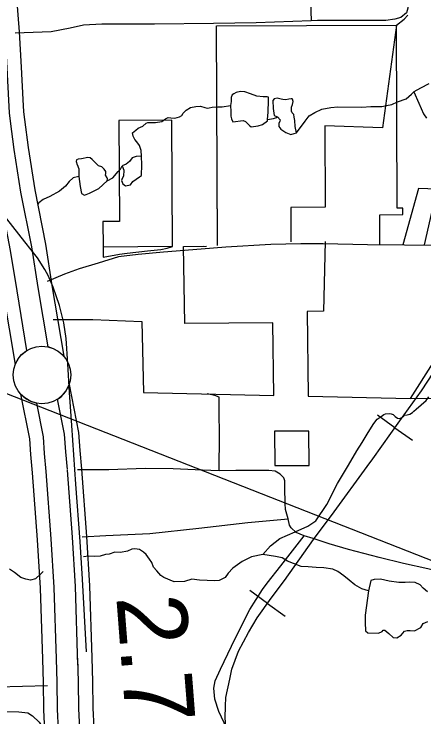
# Model space of a CAD drawing. Extents: x 22866 to 28196, y 1324810 to 1328105.
# Drawn here: x 25705 to 25764.8, y 1326340.7 to 1326443.3 of the extents above; entities that cross this region are included whole.
import ezdxf

# ---------------------------------------------------------------- set-up
doc = ezdxf.new("R2010")
doc.units = 0
for name, color, linetype in [('Level 15', 7, 'Continuous'), ('Level 24', 7, 'Continuous'), ('Level 33', 7, 'Continuous'), ('Level 35', 7, 'Continuous'), ('Level 40', 7, 'Continuous'), ('Level 48', 7, 'Continuous'), ('Level 5', 7, 'Continuous'), ('Level 6', 7, 'Continuous'), ('Page Text', 7, 'Continuous')]:
    doc.layers.add(name, color=color, linetype=linetype)

msp = doc.modelspace()

# ---------------------------------------------------------------- linework, layer by layer
at = {"layer": 'Level 15'}
for points in [[(25705.13, 1326448.21), (25705.72, 1326440.72), (25706.02, 1326435.56), (25706.28, 1326430.85), (25706.38, 1326429.05), (25706.49, 1326427.91), (25707.03, 1326423.82), (25708.01, 1326417.65), (25709.58, 1326409.7), (25710.51, 1326403.7), (25712.25, 1326393.35)], [(25697.94, 1326447.76), (25698.53, 1326440.23), (25698.83, 1326435.16), (25699.09, 1326430.45), (25699.2, 1326428.49), (25699.34, 1326427.08), (25699.9, 1326422.79), (25700.92, 1326416.4), (25702.48, 1326408.44), (25703.41, 1326402.55), (25705.15, 1326392.16), (25705.7, 1326393.12), (25706.12, 1326393.62), (25706.87, 1326394.21)], [(25706.87, 1326394.21), (25705.42, 1326402.88), (25704.49, 1326408.8), (25702.92, 1326416.75), (25701.92, 1326423.08), (25701.37, 1326427.32), (25701.23, 1326428.65), (25701.13, 1326430.57), (25700.86, 1326435.27), (25700.57, 1326440.37), (25699.98, 1326447.89)], [(25712.25, 1326393.35), (25711.41, 1326394.06), (25710.73, 1326394.44), (25709.95, 1326394.72), (25708.5, 1326403.37), (25707.57, 1326409.34), (25706, 1326417.3), (25705.01, 1326423.53), (25704.47, 1326427.68), (25704.34, 1326428.89), (25704.24, 1326430.74), (25703.98, 1326435.45), (25703.68, 1326440.58), (25703.09, 1326448.08)], [(25711.35, 1326387.1), (25711.86, 1326387.44), (25712.52, 1326388.22), (25713.01, 1326389.2), (25714.4, 1326382.23), (25714.57, 1326379.57), (25714.83, 1326376.86)], [(25708.29, 1326386.49), (25707.42, 1326386.73), (25706.57, 1326387.25), (25705.95, 1326387.79), (25707.24, 1326381.29), (25707.39, 1326378.99), (25707.65, 1326376.34)], [(25709.68, 1326376.49), (25709.42, 1326379.16), (25709.27, 1326381.56), (25708.29, 1326386.49)], [(25712.79, 1326376.83), (25712.53, 1326379.41), (25712.37, 1326381.96), (25711.35, 1326387.1)], [(25707.65, 1326376.34), (25708.36, 1326366.55), (25708.81, 1326359.49), (25709.14, 1326349.1)], [(25711.18, 1326349.16), (25710.85, 1326359.58), (25710.39, 1326366.69), (25709.68, 1326376.49)], [(25714.29, 1326348.23), (25713.96, 1326359.73), (25713.51, 1326366.9), (25712.8, 1326376.71)], [(25714.83, 1326376.86), (25715.54, 1326367.04), (25716, 1326359.83), (25716.34, 1326349.31)], [(25709.14, 1326349.1), (25709.24, 1326345.7), (25709.3, 1326341.72), (25709.43, 1326338.66)], [(25711.47, 1326338.79), (25711.34, 1326341.78), (25711.28, 1326345.74), (25711.18, 1326349.16)], [(25714.58, 1326339), (25714.46, 1326341.87), (25714.4, 1326345.81), (25714.3, 1326349.25)], [(25716.34, 1326349.31), (25716.44, 1326345.86), (25716.5, 1326341.93), (25716.62, 1326339.14)]]:
    msp.add_lwpolyline(points, dxfattribs=at)
at = {"layer": 'Level 24'}
msp.add_circle((25709.06, 1326390.62), 4.2, dxfattribs=at)
at = {"layer": 'Level 33'}
for points in [[(25762.61, 1326449.5), (25762.56, 1326446.04), (25762.43, 1326444.19), (25762.21, 1326443.51), (25761.4, 1326442.82), (25760.55, 1326442.58), (25759.21, 1326442.37), (25756.24, 1326442.4), (25749.25, 1326442.4), (25748.32, 1326442.35), (25740.32, 1326442.04), (25734.08, 1326441.95)], [(25748.09, 1326447.31), (25748.22, 1326445.09), (25748.32, 1326442.35)], [(25734.08, 1326441.95), (25725.49, 1326441.87), (25717.81, 1326441.87), (25715.13, 1326441.69), (25713.16, 1326441.24), (25710.42, 1326440.73), (25705.13, 1326440.55)], [(25746.83, 1326409.77), (25742.43, 1326409.69), (25735.9, 1326409.3), (25732.26, 1326408.99), (25726.8, 1326408.53), (25723.07, 1326408.2)], [(25761.94, 1326409.56), (25756.54, 1326409.63), (25750.08, 1326409.77), (25746.83, 1326409.77)], [(25776.52, 1326409.39), (25769.38, 1326409.51), (25761.94, 1326409.56)], [(25723.07, 1326408.2), (25720.23, 1326407.85), (25717.27, 1326406.96), (25714.51, 1326406.1), (25712.34, 1326405.33), (25709.82, 1326404.25)], [(25734.92, 1326376.61), (25734.97, 1326381.93), (25734.9, 1326385.13), (25734.93, 1326387.17), (25734.9, 1326387.38), (25734.27, 1326387.63), (25733.18, 1326387.84)], [(25747.3, 1326367.13), (25746.16, 1326367.61), (25745.42, 1326368.31), (25745.18, 1326368.7), (25744.96, 1326369.61), (25744.58, 1326370.95), (25744.54, 1326371.86), (25744.47, 1326374.15), (25744.47, 1326375.13), (25744.33, 1326375.59), (25743.81, 1326376.11), (25743.1, 1326376.54), (25742.16, 1326376.64), (25740.16, 1326376.68), (25737.35, 1326376.68), (25734.92, 1326376.61), (25732.48, 1326376.71), (25728.19, 1326376.92), (25724.12, 1326376.96), (25718.82, 1326376.78), (25714.24, 1326376.78)], [(25714.94, 1326366.99), (25718.37, 1326367.15), (25724.8, 1326367.44), (25731.92, 1326368.24), (25739.08, 1326369.05), (25742.82, 1326369.4), (25744.96, 1326369.61)], [(25739.05, 1326331.7), (25737.72, 1326335.37), (25736.38, 1326338.25), (25734.87, 1326341.45), (25734.27, 1326343.24), (25734.13, 1326344.89), (25734.31, 1326345.95), (25735.12, 1326347.63), (25737.22, 1326352.1), (25739.37, 1326356.36), (25741.23, 1326359.28), (25741.89, 1326360.19), (25743.89, 1326362.72), (25747.3, 1326367.13)], [(25748.64, 1326366.73), (25747.3, 1326367.13)], [(25788.31, 1326360.11), (25786.8, 1326360.46), (25783.79, 1326360.98), (25781.97, 1326361.17), (25780.19, 1326361.37), (25776.59, 1326361.58), (25773.86, 1326361.56), (25770.8, 1326361.54), (25768.83, 1326361.64), (25767.48, 1326361.74), (25765.33, 1326362.28), (25761.79, 1326363.09), (25758.26, 1326363.94), (25753.75, 1326365.1), (25750.93, 1326365.94), (25748.64, 1326366.73)], [(25685.48, 1326344.66), (25687.91, 1326344.69), (25694.32, 1326344.87), (25699.58, 1326344.99), (25702.54, 1326345.08), (25709.86, 1326345.26)], [(25684.81, 1326334.32), (25684.32, 1326334.65), (25684.18, 1326335), (25684.11, 1326335.67), (25684.28, 1326336.23), (25685.55, 1326337.92), (25687.09, 1326339.78), (25688.36, 1326340.73), (25689.73, 1326341.15), (25692.22, 1326341.26), (25696.08, 1326341.29), (25700.82, 1326341.4), (25703.7, 1326341.47), (25705.7, 1326341.4), (25707, 1326341.29), (25707.67, 1326340.83), (25708.65, 1326339.92), (25709.14, 1326339.18), (25709.42, 1326338.48), (25709.45, 1326337.66)]]:
    msp.add_lwpolyline(points, dxfattribs=at)
at = {"layer": 'Level 35'}
for points in [[(25765.49, 1326433.15), (25764.26, 1326432.52), (25763.32, 1326431.98)], [(25736.91, 1326427.57), (25738.39, 1326427.8), (25738.73, 1326427.64), (25739.33, 1326427.04), (25739.59, 1326426.85), (25740.61, 1326427.01), (25741.24, 1326427.19), (25741.95, 1326427.72), (25741.95, 1326427.9), (25742.08, 1326429), (25742.1, 1326430.7), (25742.1, 1326431.17), (25741.92, 1326431.25), (25741.32, 1326431.25), (25740.4, 1326431.35), (25739.49, 1326431.69), (25738.63, 1326431.96), (25738, 1326432.01), (25737.37, 1326431.88), (25737.06, 1326431.69), (25736.82, 1326431.51), (25736.67, 1326431.14), (25736.64, 1326430.54), (25736.56, 1326429.99), (25736.59, 1326429.08), (25736.59, 1326428.42), (25736.72, 1326428.01), (25736.91, 1326427.57)], [(25746.21, 1326425.99), (25747.43, 1326427.69), (25748.06, 1326428.45), (25748.84, 1326428.95), (25749.89, 1326429.44), (25751.19, 1326429.68), (25752.21, 1326429.78), (25755.72, 1326429.71), (25757.05, 1326429.81), (25758.62, 1326429.84), (25759.32, 1326429.97), (25760.11, 1326430.1), (25760.94, 1326430.48), (25762.17, 1326430.93), (25762.95, 1326431.63), (25763.32, 1326431.98)], [(25763.32, 1326431.98), (25764.05, 1326430.32), (25764.73, 1326428.75), (25765.17, 1326428.1)], [(25743.93, 1326430.91), (25743.38, 1326431.04), (25742.94, 1326430.96), (25742.73, 1326430.7), (25742.78, 1326429.55), (25742.94, 1326428.5), (25743.41, 1326428.32), (25743.8, 1326427.87), (25743.78, 1326427.67), (25743.59, 1326427.35), (25743.59, 1326427.22), (25743.62, 1326426.88), (25743.91, 1326426.51), (25744.64, 1326426.02), (25745.37, 1326425.73), (25745.87, 1326425.86), (25746.21, 1326425.99), (25746, 1326426.91), (25745.97, 1326427.8), (25745.87, 1326428.27), (25745.79, 1326428.63), (25745.58, 1326428.89), (25745.45, 1326429.13), (25745.45, 1326429.34), (25745.48, 1326429.71), (25745.61, 1326430.12), (25745.68, 1326430.57), (25745.61, 1326430.91), (25745.55, 1326430.96), (25745.4, 1326430.96), (25745.06, 1326430.88), (25744.61, 1326430.8), (25744.19, 1326430.86), (25743.93, 1326430.88)], [(25725.6, 1326427.51), (25726.54, 1326427.61), (25727.09, 1326428.01), (25727.48, 1326428.21), (25727.85, 1326428.19), (25728.42, 1326428.14), (25729.13, 1326428.29), (25729.44, 1326428.5), (25729.67, 1326428.84), (25730.09, 1326429.31), (25730.75, 1326429.68), (25731.5, 1326429.84), (25732.18, 1326429.86), (25732.84, 1326429.68), (25733.18, 1326429.6), (25733.44, 1326429.65), (25733.88, 1326429.73), (25734.72, 1326429.76), (25735.37, 1326429.78), (25736.56, 1326429.99)], [(25741.95, 1326427.9), (25742.81, 1326428.08), (25743.25, 1326428.21), (25743.41, 1326428.32)], [(25723.59, 1326422.57), (25723.54, 1326423.41), (25723.3, 1326424.11), (25722.91, 1326424.64), (25722.6, 1326425), (25722.34, 1326425.47), (25722.28, 1326426), (25722.73, 1326426.36), (25723.07, 1326426.68), (25723.75, 1326426.96), (25724.24, 1326427.38), (25724.5, 1326427.49), (25724.98, 1326427.51), (25725.6, 1326427.51)], [(25720.75, 1326421.15), (25721, 1326420.53), (25720.95, 1326419.66), (25720.77, 1326419.32), (25720.66, 1326419.01), (25720.85, 1326418.51), (25721.26, 1326418.25), (25721.97, 1326418.38), (25722.31, 1326418.85), (25723.28, 1326419.53), (25723.59, 1326419.74), (25723.64, 1326421.29), (25723.59, 1326422.57), (25722.78, 1326422.54), (25722.2, 1326422.31), (25721.81, 1326421.81), (25721.32, 1326421.39), (25720.75, 1326421.15)], [(25714.18, 1326421.37), (25714.42, 1326420.71), (25714.44, 1326419.59), (25714.65, 1326418.15), (25714.83, 1326417.1), (25715.25, 1326416.89), (25715.98, 1326417.15), (25717.37, 1326417.83), (25718.55, 1326418.96), (25718.6, 1326419.25), (25718.55, 1326419.4), (25718.34, 1326419.8), (25718.36, 1326420.03), (25718.36, 1326420.34), (25718.15, 1326420.69), (25717.79, 1326421), (25717.29, 1326421.18), (25716.98, 1326421.52), (25716.66, 1326421.81), (25716.38, 1326422.1), (25716.11, 1326422.33), (25715.75, 1326422.36), (25714.83, 1326422.2), (25714.34, 1326422.12), (25714.1, 1326422.02), (25714.05, 1326421.78), (25714.18, 1326421.31)], [(25718.55, 1326418.96), (25719.41, 1326419.4), (25720.19, 1326420.32), (25720.51, 1326420.69), (25720.75, 1326421.15)], [(25714.44, 1326419.59), (25713.6, 1326419.42), (25713.02, 1326418.87), (25712.5, 1326418.17), (25711.64, 1326417.44), (25710.2, 1326416.68), (25709.23, 1326416.26), (25708.61, 1326415.74), (25708.44, 1326415.46)], [(25756.65, 1326382.23), (25757.45, 1326383.54), (25757.96, 1326384.17), (25758.54, 1326384.56), (25758.95, 1326384.85), (25759.19, 1326384.95), (25759.71, 1326384.99), (25760.01, 1326384.95), (25760.28, 1326384.83), (25760.59, 1326384.53), (25760.91, 1326384.29), (25761.19, 1326384.24), (25761.48, 1326384.35), (25761.78, 1326384.56), (25761.94, 1326384.72), (25762.33, 1326384.81), (25762.71, 1326384.9), (25763.1, 1326385.15), (25763.29, 1326385.33), (25763.65, 1326385.6), (25765.11, 1326386.87), (25765.47, 1326387.44)], [(25752.15, 1326374.78), (25753.78, 1326377.45), (25754.97, 1326379.55), (25755.79, 1326380.77), (25756.65, 1326382.23)], [(25741.29, 1326364.38), (25742.39, 1326365.65), (25743.78, 1326366.72), (25745.99, 1326367.72), (25747.84, 1326368.54), (25749.02, 1326369.29), (25750.62, 1326371.71), (25752.15, 1326374.78), (25753.33, 1326376.71)], [(25741.29, 1326364.38), (25739.64, 1326364.06), (25738.26, 1326363.38), (25736.9, 1326362.39), (25736.22, 1326361.68), (25735.78, 1326361.03), (25734.91, 1326360.61), (25734.23, 1326360.56), (25733.14, 1326360.58), (25732.04, 1326360.64), (25730.94, 1326360.79), (25729.87, 1326360.43), (25728.33, 1326360.4), (25726.85, 1326361.05), (25726.39, 1326361.32), (25725.82, 1326362), (25725.32, 1326362.55), (25725.09, 1326363.2), (25724.77, 1326363.72), (25724.25, 1326364.38), (25723.86, 1326364.74), (25723.31, 1326365.11), (25722.63, 1326365.21), (25722.18, 1326365.16), (25721.53, 1326364.87), (25720.54, 1326364.67), (25719.7, 1326364.72), (25718.85, 1326364.46)], [(25718.85, 1326364.46), (25718.35, 1326364.4), (25717.55, 1326364.15), (25716.73, 1326364.09), (25715.84, 1326364.17), (25715.13, 1326364.07)], [(25756.7, 1326359.09), (25755.71, 1326359.38), (25754.72, 1326359.96), (25753.88, 1326360.66), (25753.07, 1326361.29), (25752.24, 1326361.89), (25751.48, 1326362.26), (25750.17, 1326362.44), (25749.07, 1326362.49), (25747.87, 1326362.6), (25746.85, 1326362.62), (25745.76, 1326363.1), (25744.89, 1326363.44), (25744.08, 1326363.91), (25743.12, 1326364.12), (25741.29, 1326364.38)], [(25709.26, 1326361.89), (25708.92, 1326361.55), (25708.13, 1326360.85), (25707.37, 1326360.64), (25706.69, 1326360.77), (25705.96, 1326361.03), (25705.07, 1326361.74), (25704.32, 1326362.23)], [(25765.3, 1326358.94), (25764.67, 1326359.49), (25764.23, 1326359.96), (25763.5, 1326360.3), (25762.74, 1326360.35), (25762.06, 1326360.3), (25761.12, 1326360.32), (25759.71, 1326360.51), (25758.45, 1326360.77), (25757.51, 1326360.74), (25757.02, 1326360.61), (25756.7, 1326359.09), (25756.21, 1326355.51), (25756.21, 1326354.44), (25756.26, 1326353.26), (25756.6, 1326352.97), (25758.17, 1326352.92), (25758.69, 1326353.15), (25758.82, 1326353.36), (25759.08, 1326353.34), (25759.68, 1326352.84), (25760.31, 1326352.29), (25760.81, 1326352.24), (25761.46, 1326352.6), (25761.96, 1326353.18), (25762.35, 1326353.28), (25762.77, 1326353.28), (25763.42, 1326353.23), (25764.31, 1326353.73), (25764.67, 1326354.3), (25765.33, 1326354.59)]]:
    msp.add_lwpolyline(points, dxfattribs=at)
at = {"layer": 'Level 40'}
for p, q in [((25760.55, 1326382.91), (25757.98, 1326384.75)), ((25760.55, 1326382.91), (25763.13, 1326381.07)), ((25741.97, 1326357.25), (25739.4, 1326359.11)), ((25741.97, 1326357.25), (25744.53, 1326355.4))]:
    msp.add_line(p, q, dxfattribs=at)
for points in [[(25710.7, 1326403.45), (25709.98, 1326405.14), (25709.48, 1326406.02), (25708.41, 1326407.74), (25706.58, 1326410.07), (25703.07, 1326414.54), (25701.08, 1326417.18), (25699.4, 1326420.4), (25698.37, 1326422.54), (25697.61, 1326424.56), (25697.07, 1326426.78), (25696.77, 1326429.49), (25696.62, 1326431.75), (25696.69, 1326433.62), (25696.73, 1326435.04), (25697.38, 1326438.02), (25697.72, 1326439.67), (25698.83, 1326442.61), (25700.43, 1326445.66), (25701.85, 1326448.07), (25704.14, 1326451.24), (25706.27, 1326454.15)], [(25714.97, 1326360.79), (25714.63, 1326366.28), (25714.02, 1326374.68), (25713.41, 1326383.22), (25713.07, 1326388.05), (25712.84, 1326392.25), (25712.57, 1326395.96), (25712.23, 1326398.25), (25711.62, 1326400.77), (25710.7, 1326403.45)], [(25735.77, 1326340.55), (25735.84, 1326342.22), (25735.88, 1326343.5), (25736.46, 1326346.16), (25736.76, 1326347.63), (25737.75, 1326350.27), (25739.19, 1326353), (25740.45, 1326355.16), (25742.5, 1326358), (25744.42, 1326360.6), (25748.67, 1326366.6), (25751.67, 1326370.6), (25756.49, 1326377.24), (25757.31, 1326378.37), (25761.27, 1326383.91), (25764.4, 1326388.3), (25772.77, 1326401.09)], [(25744.42, 1326360.6), (25748.67, 1326366.6), (25751.67, 1326370.6), (25756.49, 1326377.24), (25757.31, 1326378.37), (25761.27, 1326383.91), (25764.4, 1326388.3)], [(25715.56, 1326350.17), (25714.97, 1326360.79)], [(25748.38, 1326315.21), (25747.73, 1326316.73), (25747.29, 1326317.52), (25746.33, 1326319.06), (25744.69, 1326321.14), (25741.55, 1326325.14), (25739.77, 1326327.5), (25738.27, 1326330.39), (25737.34, 1326332.3), (25736.66, 1326334.12), (25736.18, 1326336.1), (25735.91, 1326338.53), (25735.77, 1326340.55), (25735.84, 1326342.22), (25735.88, 1326343.5), (25736.46, 1326346.16), (25736.76, 1326347.63), (25737.75, 1326350.27), (25739.19, 1326353), (25740.45, 1326355.16), (25742.5, 1326358), (25744.42, 1326360.6)]]:
    msp.add_lwpolyline(points, dxfattribs=at)
at = {"layer": 'Level 5'}
msp.add_lwpolyline([(25728.11, 1326409.37), (25717.98, 1326409.3)], dxfattribs=at)
at = {"layer": 'Level 6'}
for points in [[(25760.76, 1326441.71), (25761.91, 1326442.56), (25762.41, 1326443.14)], [(25734.65, 1326409.54), (25734.5, 1326441.61), (25760.76, 1326441.71)], [(25734.65, 1326409.57), (25734.5, 1326441.61), (25760.76, 1326441.71), (25758.74, 1326426.73), (25750.3, 1326426.98), (25750.36, 1326415.12), (25745.35, 1326415.09), (25745.37, 1326410.08)], [(25760.76, 1326441.71), (25758.74, 1326426.73), (25750.3, 1326426.98), (25750.36, 1326415.12), (25745.35, 1326415.09), (25745.37, 1326410.17)], [(25758.35, 1326409.7), (25758.33, 1326414.02), (25761.69, 1326414.04), (25761.69, 1326414.99), (25760.89, 1326414.98), (25760.76, 1326441.71)], [(25764.84, 1326409.62), (25766.69, 1326417.77), (25764, 1326417.85), (25761.72, 1326409.62)], [(25750.38, 1326410.11), (25750.13, 1326399.91), (25747.73, 1326399.89), (25747.91, 1326387.52), (25762.83, 1326387.18)], [(25750.38, 1326410.1), (25750.13, 1326399.91), (25747.73, 1326399.89), (25747.91, 1326387.52), (25762.83, 1326387.18), (25776.83, 1326387.3), (25790.5, 1326387.37), (25790.64, 1326382.09), (25795.44, 1326382.26), (25795.52, 1326377.48), (25837.59, 1326377.54), (25837.63, 1326377.54)], [(25710.68, 1326398.71), (25716.47, 1326398.71), (25723.64, 1326398.44), (25723.88, 1326388.06), (25742.9, 1326387.63), (25742.74, 1326398.21), (25729.9, 1326398.13), (25729.73, 1326409.38), (25732.66, 1326409.4)], [(25710.79, 1326398.71), (25716.47, 1326398.71), (25723.64, 1326398.44), (25723.88, 1326388.06), (25742.9, 1326387.63), (25742.74, 1326398.21), (25729.9, 1326398.13), (25729.73, 1326409.38), (25733.07, 1326409.4)], [(25762.83, 1326387.18), (25777.05, 1326409.63), (25776.83, 1326387.3)]]:
    msp.add_lwpolyline(points, dxfattribs=at)
for points in [[(25728.11, 1326409.37), (25728.02, 1326427.83), (25720.29, 1326427.78), (25720.36, 1326413.04), (25717.96, 1326413.02), (25717.98, 1326409.3), (25717.99, 1326407.8), (25720.39, 1326408.24), (25721.47, 1326408.4), (25724.44, 1326408.73), (25726.38, 1326408.93), (25727.33, 1326409.11)], [(25748.06, 1326377.4), (25747.99, 1326382.41), (25742.98, 1326382.4), (25743.05, 1326377.39)]]:
    msp.add_lwpolyline(points, close=True, dxfattribs=at)
at = {"layer": 'Page Text'}
msp.add_lwpolyline([(25620.91, 1326420.53), (26211.65, 1326188.26)], dxfattribs=at)

# ---------------------------------------------------------------- texts
at = {"layer": 'Level 48'}
msp.add_text('2.7', height=10.139, rotation=274.4321, dxfattribs=at).set_placement((25719.9, 1326358.19))

doc.saveas('drawing.dxf')
